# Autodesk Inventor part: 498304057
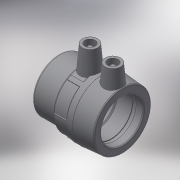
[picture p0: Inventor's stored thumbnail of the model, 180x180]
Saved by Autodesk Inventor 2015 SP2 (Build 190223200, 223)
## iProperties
Created: 2017-06
Part Number: 498304057
Material: Generic
Description: PLASSON WELDING CAP FOR TAPPING SADDLE TYPE-A
Document SubType Name: Modeling
Designer: KIM
Density: 1 g/cm^3
Appearance: Default
Author: KIM
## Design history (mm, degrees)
derived "498304_2.ipt"
feature "Solid1::498304_2.ipt"
tag "TaggingFeature1"
body "Solid1"
other parameters: "d7" = 2.22, "d8" = 22.05, "d10" = 1.48, "d11" = 12.6, "d12" = 168 deg, "d13" = 4.2, "d14" = 58.9, "d15" = 59, "d16" = 15, "d17" = 37, "d18" = 1, "d20" = 5 deg, "d21" = 53.1, "d22" = 15, "d26" = 5 deg, "d27" = 4, "d29" = 14, "d30" = 0, "d31" = 4, "d33" = 14, "d34" = 0, "d46" = 3, "d47" = 0, "d48" = 3, "d49" = 0, "d50" = 74, "d51" = 74, "d52" = 81.4, "d53" = 84.36, "d54" = 63, "d55" = 135 deg, "d56" = 36, "d57" = 55.955, "d58" = 53.01, "d59" = 72.52, "d60" = 48.1, "d61" = 11.1, "d62" = 2.945, "d63" = 5.89, "d64" = 2.945, "d66" = 0, "d67" = 60 deg, "d69" = 360 deg, "d71" = 3.7, "d74" = 5.18, "d_" = 58.9, "L_" = 63, "L_1" = 36, "D_" = 74, "A_" = 59, "H_" = 74
